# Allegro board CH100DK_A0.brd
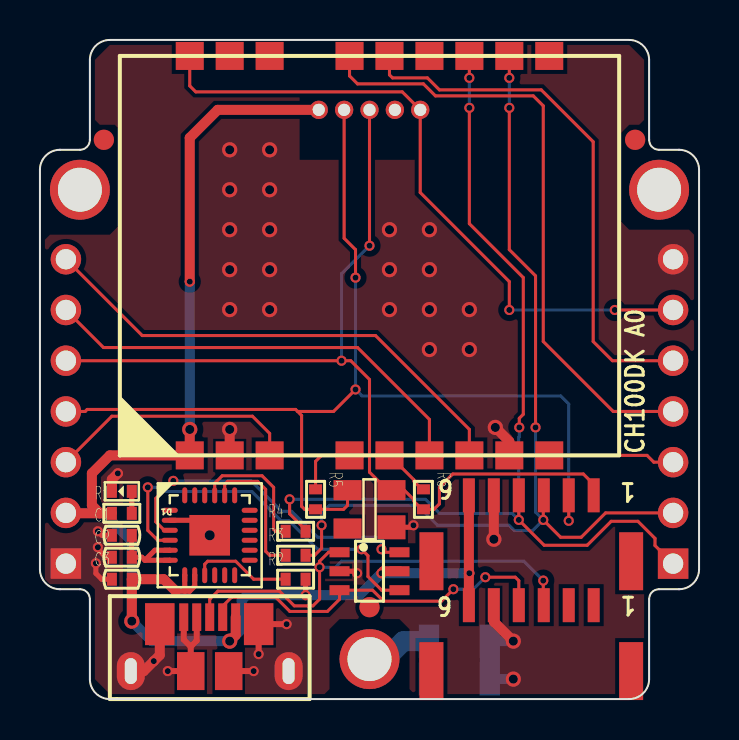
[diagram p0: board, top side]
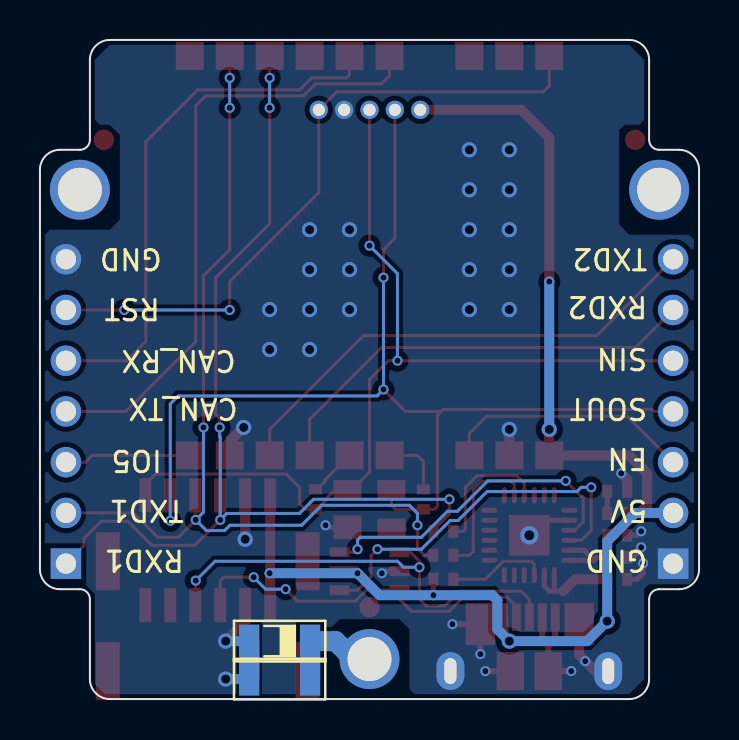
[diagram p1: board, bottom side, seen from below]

Outline 33 x 33 mm; copper layers: TOP, BOTTOM. Coordinates in mm from the lower left corner of the outline.
Outline path: 0,26.5 0,6.5 arc(0.29,5.79) 1,5.5 2,5.5 arc(2.35,5.35) 2.5,5 2.5,1 arc(2.79,0.29) 3.5,0 29.5,0 arc(30.21,0.29) 30.5,1 30.5,5 arc(30.65,5.35) 31,5.5 32,5.5 arc(32.71,5.79) 33,6.5 33,26.5 arc(32.71,27.21) 32,27.5 31,27.5 arc(30.65,27.65) 30.5,28 30.5,32 arc(30.21,32.71) 29.5,33 3.5,33 arc(2.79,32.71) 2.5,32 2.5,28 arc(2.35,27.65) 2,27.5 1,27.5 arc(0.29,27.21) 0,26.5

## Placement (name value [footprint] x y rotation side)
C1  1uF  [C0402]  4.1 8.2 0 top
C2  0.1uF  [C0402]  4.1 7.1 0 top
C3  1uF  [C0402]  4.1 6 0 top
C13  1000pF 1KV  [SC1206]  21 2.9 0 bottom
D1  RED  [LED0402]  4.1 10.4 180 top
D6  SR05  [SOT-143]  16.5 9.5 90 top
H1  HOLE  [HOLE-2-MM]  16.5 2 0 top
H2  HOLE  [HOLE-2-MM]  2 25.5 0 top
H3  HOLE  [HOLE-2-MM]  31 25.5 0 top
J1  MINI-USB  [MICRO-USB-B-1051640001]  8.5 4.1 90 top
J2  HEADER 5  [HEADER1X5-1_27MM]  16.5 29.5 0 bottom
J3  CON6  [A1257WV-S-6P]  24.6 4.7 180 top
J4  CON6  [A1257WV-S-6P]  24.6 10.2 180 top
J5  CON7  [HEADER1X7-2_54MM]  31.7 14.4 90 top
J6  CON7  [HEADER1X7-2_54MM]  1.3 14.4 90 top
NOREF  -  []  2 25.5 0 top
R1  330R  [R0402]  4.1 9.3 0 top
R2  4.7K  [R0402]  12.8 6 0 top
R3  1K  [R0402]  12.8 7.2 0 top
R4  1K  [R0402]  12.8 8.4 0 top
R5  1K  [R0402]  13.8 10 270 top
R6  1K  [R0402]  19.2 10 270 top
R21  1M  [SR1206]  21 1 180 bottom
TP1  TestPoint  [TP-C-40]  3.2 28 0 top
TP2  TestPoint  [TP-C-40]  29.8 28 0 top
TP3  TestPoint  [TP-C-40]  16.5 4.6 0 top
U1  USBLC6-2SC6  [SOT23-6-0_95]  16.5 6.4 270 top
U2  CP2104  [QFN-24_4X4MM_P0_5]  8.5 8.2 0 top
U3  CH100  [CH100_MINI]  16.5 22.2 90 top

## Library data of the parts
C1-C3 C13 = Capacity_Nonpolarity
D1 = LED
D6 = SP0503BAHT
H1-H3 = HOLE
J1 = MICRO-USB_B
J2 = HEADER 5
J3 J4 = CON6
J5 J6 = CON7
R1-R6 R21 = Res
TP1-TP3 = TestPoint
U1 = USBLC6-2SC6
U2 = CP2104
U3 = CH100

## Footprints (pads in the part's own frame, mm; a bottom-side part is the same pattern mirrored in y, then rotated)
A1257WV-S-6P
  rect 1.2x2.9 smd: (-5,3.3) (5,3.3)
  rect 0.6x1.7 smd: 1(-3.125,0) 2(-1.875,0) 3(-0.625,0) 4(0.625,0) 5(1.875,0) 6(3.125,0)
C0402
  rect 0.5x0.65 smd: 1(-0.5,0) 2(0.5,0)
CH100_MINI
  rect 1.4x1.4 smd: 1(-10,9) 2(-10,7) 3(-10,5) 4(-10,1) 5(-10,-1) 6(-10,-3) 7(-10,-5) 8(-10,-7) 9(-10,-9) 10(10,-9) 11(10,-7) 12(10,-5) 13(10,-3) 14(10,-1) 15(10,1) 16(10,5) 17(10,7) 18(10,9)
HEADER1X5-1_27MM
  round 0.914 hole 0.61: 1(-2.54,0) 2(-1.27,0) 3(0,0) 4(1.27,0) 5(2.54,0)
HEADER1X7-2_54MM
  rect 1.524x1.524 hole 1.016: 1(-7.62,0)
  round 1.524 hole 1.016: 2(-5.08,0) 3(-2.54,0) 4(0,0) 5(2.54,0) 6(5.08,0) 7(7.62,0)
HOLE-2-MM
  round 3 hole 2.2: 1(0,0)
LED0402
  rect 0.5x0.65 smd: 1(-0.5,0) 2(0.5,0)
MICRO-USB-B-1051640001
  rect 1.38x0.45 smd: 1(0,-1.3) 2(0,-0.65) 3(0,0) 4(0,0.65) 5(0,1.3)
  rect 2.1x1.475 smd: 6(-0.35,-2.45) 9(-0.35,2.5)
  oval 1.9x1.4 hole 1.3x0.6: 7(-2.7,3.95) 8(-2.7,-3.95)
  rect 1.9x1.375 smd: 10(-2.7,-0.95) 11(-2.7,0.95)
QFN-24_4X4MM_P0_5
  oval 0.8x0.25 smd: 1(-2,1.25) 2(-2,0.75) 3(-2,0.25) 4(-2,-0.25) 5(-2,-0.75) 6(-2,-1.25) 13(2,-1.25) 14(2,-0.75) 15(2,-0.25) 16(2,0.25) 17(2,0.75) 18(2,1.25)
  oval 0.25x0.8 smd: 7(-1.25,-2) 8(-0.75,-2) 9(-0.25,-2) 10(0.25,-2) 11(0.75,-2) 12(1.25,-2) 19(1.25,2) 20(0.75,2) 21(0.25,2) 22(-0.25,2) 23(-0.75,2) 24(-1.25,2)
  rect 2.032x2.032 smd: 25(0,0)
R0402
  rect 0.5x0.65 smd: 1(-0.5,0) 2(0.5,0)
SC1206
  rect 1.016x1.651 smd: 1(-1.524,0) 2(1.524,0)
SOT23-6-0_95
  rect 0.5x1 smd: 1(-0.95,-1.5) 2(0,-1.5) 3(0.95,-1.5) 4(0.95,1.5) 5(0,1.5) 6(-0.95,1.5)
SOT-143
  rect 1.2x1.4 smd: 1(-0.9,-1.1)
  rect 1x1.4 smd: 2(0.96,-1.1) 3(0.96,1.1) 4(-0.96,1.1)
SR1206
  rect 1.016x1.651 smd: 1(-1.524,0) 2(1.524,0)
TP-C-40
  round 1.016 smd: 1(0,0)

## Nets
GND: C1.1 C2.1 C3.1 C13.2 D1.2(-) D6.1 J1.4(ID) J1.5(GND) J1.6 J1.7 J1.8 J1.9 J1.10 J1.11 J2.4 J3.5 J4.5 J5.7 J6.1 R21.1 U1.2(GND) U2.2(GND) U2.25(EPD) U3.2(GND#2) U3.8(GND#8)
CAN_RX: J5.5 U3.14(CAN_RX)
CAN_TX: J5.4 U3.15(CAN_TX)
CP2104_RXD: R3.1 U2.20(RXD)
CP2104_TXD: R4.1 U2.21(TXD)
DN: J1.2(DN) J3.4 U1.3(IO2#3)
DP: J1.3(DP) J3.3 U1.1(IO1#1)
DP5V: C3.2 J1.1(VBUS) J2.1 J3.6 J4.6 J6.2 R1.1 R2.2 U1.5(VBUS) U2.7(REGIN) U2.8(VBUS) U3.1(VCC)
EN: J6.3 U3.3(EN)
IMU_RXD1: J4.4 J5.1 R4.2 U3.12(RXD1)
IMU_TXD1: J4.3 J5.2 R3.2 U3.11(TXD1)
IO5: J5.3 U3.9(IO5)
NRST: J2.5 J5.6 U3.18(NRST)
RXD2: J6.6 U3.6(RXD2)
SYNC_IN: D6.2 J2.3 J4.1 J6.5 R6.2
SYNC_OUT: D6.3 J2.2 J4.2 J6.4 R5.2
TXD2: J6.7 U3.7(TXD2)
USB_DN: U1.4(IO2#4) U2.4(D-)
USB_DP: U1.6(IO1#6) U2.3(D+)
N02222: C1.2 C2.2 U2.5(VIO) U2.6(VDD)
N03180: R2.1 U2.9(R\S\T\)
N94151: D1.1(+) R1.2
N722959: R5.1 U3.4(SYNC_OUT)
N722963: R6.1 U3.5(SYNC_IN)
N726760: C13.1 H1.1 R21.2

Pads without a net: D6 4; H2 1; H3 1; J3 1 2; TP1 1; TP2 1; TP3 1; U2 1 10 11 12 13 14 15 16 17 18 19 22 23 24; U3 10 13 16 17

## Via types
v1: diameter 0.508, hole 0.305, TOP to BOTTOM, 40 vias
v2: diameter 0.762, hole 0.457, TOP to BOTTOM, 27 vias
v3: diameter 0.914, hole 0.508, TOP to BOTTOM, 1 via

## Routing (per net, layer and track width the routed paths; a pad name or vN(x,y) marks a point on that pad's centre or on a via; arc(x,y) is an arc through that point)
GND: length 33.6
  TOP w0.254: C1.1 3.1,8.2 v1(2.9,8.4) ; C3.1 3.09,6 2.8,6.29 v1(2.8,6.8) ; D6.1 18.6,8.6 v1(18.7,8.7) ; v1(15.88,6.3) 15.8,6.3 15.7,6.4 U1.2 ; v1(2.9,7.6) 2.9,7.5 3.3,7.1 C2.1 ; U2.2 7.75,8.95 v3(8.5,8.2)
  TOP w0.3: J1.4 7.85,2.93 7.55,2.63 ; v1(10.95,2.25) J1.6 v1(12.35,3.75) ; 7.55,2.63 7.2,2.98 J1.5 ; 7.55,2.63 J1.11 v1(6.4,1.4) ; J1.10 v1(10.7,1.4)
  TOP w0.4: 1.62,6.78 J6.1
  TOP w0.5: v1(3.9,11.3) 3.6,11 D1.2 ; U3.2 v2(9.5,13.5) ; J4.5 v2(22.72,8) ; v2(22.8,13.6) 23.5,12.9 U3.8 ; J1.9 6,2.2 v1(5.7,1.9) 5.2,1.4 J1.7 ; v2(23.7,2.9) 22.72,3.87 J3.5
  BOTTOM w0.5: R21.1 v2(23.7,1) ; C13.2 v2(23.7,2.9)
  BOTTOM w1: R21.1 C13.2
  vias: v2(9.5,27.5) v2(9.5,25.5) v2(9.5,23.5) v2(9.5,21.5) v2(9.5,19.5) v2(11.5,27.5) v2(11.5,25.5) v2(11.5,23.5) v2(11.5,21.5) v2(11.5,19.5) v2(17.5,23.5) v2(17.5,21.5) v2(17.5,19.5) v2(19.5,23.5) v2(19.5,21.5) v2(19.5,19.5) v2(19.5,17.5) v2(21.5,19.5) v2(21.5,17.5)
CAN_RX: length 26.9
  TOP w0.152: U3.14 17.5,31.25 17.65,31.1 19.4,31.1 20,30.5 25.1,30.5 27.7,27.9 27.7,17.9 28.66,16.94 J5.5
CAN_TX: length 31.1
  TOP w0.152: U3.15 15.5,31.2 15.9,30.8 19.2,30.8 19.8,30.2 24.7,30.2 25.2,29.7 25.2,17.9 28.7,14.4 J5.4
CP2104_RXD: length 7
  TOP w0.152: R3.1 11.5,7.2 11.3,7.4 11.3,10.5 10.9,10.9 9.4,10.9 9.25,10.75 U2.20
CP2104_TXD: length 6.7
  TOP w0.152: U2.21 8.75,10.8 9.13,11.18 11.12,11.18 11.7,10.6 11.7,8.5 11.8,8.4 R4.1
DN: length 18.6
  TOP w0.152: J3.4 23.97,4.7 23.97,5.92 23.8,6.1 v1(22.3,6.1) ; J1.2 9.15,4.65 9.6,5.1 11.8,5.1 12.51,4.39 14.39,4.39 15,5 U1.3 16.66,5.45 17.21,4.9 20.1,4.9 v1(20.7,5.5)
  BOTTOM w0.152: v1(20.7,5.5) 21.7,5.5 v1(22.3,6.1)
DP: length 23.1
  TOP w0.152: J1.3 8.5,4.99 8.91,5.4 12,5.4 12.73,4.67 13.67,4.67 14,5 v1(14,6.6) 14,6.9 14.45,7.35 U1.1 ; v1(25.2,5.93) 25.2,4.72 J3.3
  BOTTOM w0.152: v1(14,6.6) 14.8,6.6 15.1,6.9 24.23,6.9 v1(25.2,5.93)
DP5V: length 75.7
  TOP w0.254: 7.26,5.4 6.8,5.4 ; 7.26,5.4 7.5,5.4 7.75,5.65 U2.8 ; 7.26,5.4 7.25,5.41 U2.7 ; R2.2 v1(13.3,5.2)
  TOP w0.5: U1.5 17.2,6.4 v1(17.1,6.3) ; 21.47,6.27 21.47,10.2 J4.6 ; 21.47,6.27 21.47,4.7 J3.6 ; 21.47,6.27 v1(21.5,6.3) ; J2.1 8.9,29.5 7.5,28.1 v1(7.5,20.9) ; 6.8,5.4 6.2,6 C3.2 v2(4.6,3.9) ; J6.2 1.32,9.3 3,9.3 ; v2(7.5,13.5) U3.1 3.5,12.2 2.6,11.3 2.6,9.7 3,9.3 ; 3,9.3 R1.1 ; J1.1 9.8,3.2 v2(9.5,2.9)
  BOTTOM w0.5: v1(21.5,6.3) v1(17.1,6.3) 16,5.2 v1(13.3,5.2) 10.35,5.2 10.1,4.95 10.1,3.5 v2(9.5,2.9) 5.6,2.9 v2(4.6,3.9) 4.6,7.9 3.18,9.32 J6.2 ; v2(7.5,13.5) v1(7.5,20.9)
EN: length 12.6
  TOP w0.152: J6.3 3.6,14.16 10.64,14.16 11.5,13.3 U3.3
IMU_RXD1: length 49.3
  TOP w0.152: J4.4 23.97,10.2 v1(23.97,8.97) 25.24,7.7 27.4,7.7 28.6,8.9 29.94,8.9 30.79,8.04 30.79,7.69 J5.1 ; R4.2 13.3,8.47 12.5,9.27 v1(12.5,10) ; v1(24,13.6) 24,14.06 24.2,14.26 24.2,21.1 21.5,23.8 v1(21.5,29.6) ; U3.12 v1(21.5,31.1)
  BOTTOM w0.152: v1(21.5,31.1) v1(21.5,29.6) ; v1(12.5,10) 19.3,10 20.01,9.29 23.65,9.29 v1(23.97,8.97) 23.97,13.12 24,13.14 v1(24,13.6)
IMU_TXD1: length 47.2
  TOP w0.152: J5.2 28.32,9.32 27.1,8.1 26.07,8.1 v1(25.2,8.97) 25.2,10.17 J4.3 ; R3.2 13.75,7.2 14.1,7.55 v1(14.1,8.7) ; U3.11 v1(23.5,31.1) ; v1(23.5,29.6) 23.5,22.5 24.81,21.19 v1(24.81,13.6)
  BOTTOM w0.152: v1(23.5,31.1) v1(23.5,29.6) ; v1(14.1,8.7) 14.1,9.3 14.5,9.7 18.9,9.7 19.9,8.7 23.49,8.7 23.75,8.44 24.67,8.44 v1(25.2,8.97) 24.81,9.36 v1(24.81,13.6)
IO5: length 6.3
  TOP w0.152: J5.3 30.73,11.86 30.39,12.2 U3.9
NRST: length 33.6
  TOP w0.152: v1(23.5,19.48) 23.5,20.9 19.04,25.36 J2.5 18.14,30.4 7.8,30.4 7.5,30.7 U3.18 ; J5.6 v1(28.78,19.48)
  BOTTOM w0.152: v1(28.78,19.48) v1(23.5,19.48)
RXD2: length 22.3
  TOP w0.152: J6.6 3.18,17.6 15.9,17.6 19.5,14 U3.6
SYNC_IN: length 47.4
  TOP w0.152: J6.5 v1(15.1,16.94) 15.56,16.94 16.5,16 16.5,11.36 17.4,10.46 D6.2 18.24,10.46 18.73,9.97 18.73,9.89 19.13,9.5 R6.2 19.73,9.5 20,9.77 20,10.6 20.67,11.27 27.21,11.27 27.72,10.75 J4.1 ; J2.3 v1(16.5,22.7)
  BOTTOM w0.152: v1(15.1,16.94) 15.1,21.3 v1(16.5,22.7)
SYNC_OUT: length 55.4
  TOP w0.152: 12.9,14.4 13.1,14.2 13.1,9.65 13.25,9.5 R5.2 15.2,9.5 15.4,9.7 D6.3 ; 12.9,14.4 12.8,14.5 2.37,14.5 2.27,14.4 J6.4 ; 12.9,14.4 14.7,14.4 v1(15.8,15.5) ; v1(15.8,21.1) 15.8,22.5 15.23,23.07 J2.2 ; J4.2 v1(26.48,8.93)
  BOTTOM w0.152: v1(26.48,8.93) 26.48,14.78 26.07,15.18 16.12,15.18 v1(15.8,15.5) v1(15.8,21.1)
TXD2: length 25
  TOP w0.152: U3.7 21.5,13.5 16.8,18.2 5.12,18.2 J6.7
USB_DN: length 18.8
  TOP w0.152: U1.4 17.11,5.45 16.42,6.13 16.42,7.18 v1(16.1,7.5) ; U2.4 5.9,7.95 5.4,8.45 v1(5.4,10.6)
  BOTTOM w0.152: v1(5.4,10.6) 5.9,10.6 6.11,10.39 10.61,10.39 12.06,8.94 12.46,8.94 13.9,7.5 v1(16.1,7.5)
USB_DP: length 16.4
  TOP w0.152: v1(6.68,10.92) 5.8,10.05 5.8,8.87 6.22,8.45 U2.3 ; v1(17.1,7.5) 17.25,7.35 U1.6
  BOTTOM w0.152: v1(6.68,10.92) 10.58,10.92 12.1,9.4 12.6,9.4 13.9,8.1 16.96,8.1 17.1,7.96 v1(17.1,7.5)
N02222: length 4.5
  TOP w0.254: C1.2 C2.2 5.1,7.1 5.25,6.95 ; 5.25,6.95 U2.6 ; 5.25,6.95 5.75,7.45 U2.5
N03180: length 5
  TOP w0.152: R2.1 10.7,6 9.8,6.9 8.4,6.9 8.25,6.75 U2.9
N94151: length 1.1
  TOP w0.254: R1.2 D1.1
N722959: length 3.2
  TOP w0.152: R5.1 13.8,11.9 14.1,12.2 U3.4
N722963: length 2.4
  TOP w0.152: R6.1 19.13,10.5 18.73,10.89 18.73,10.97 U3.5
N726760: length 5.2
  BOTTOM w1: R21.2 C13.1 18.2,2.9 17.3,2 H1.1

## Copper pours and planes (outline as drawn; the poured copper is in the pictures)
GND on TOP: 14.5,0.5 14.25,0.25 3.5,0.25 2.75,1 2.75,5.5 2.5,5.75 0.5,5.75 0.25,6 0.25,23 0.5,23.25 3.5,23.25 4,23.75 4,28.5 3.75,28.75 3,28.75 2.75,29 2.75,32 3.5,32.75 29.5,32.75 30.25,32 30.25,29 30,28.75 29.5,28.75 29,28.25 29,24 29.5,23.5 32.5,23.5 32.75,23.25 32.75,6.25 32.25,5.75 30.75,5.75 30.25,5.25 30.25,0.75 29.75,0.25 18.75,0.25 18.5,0.5 18.5,3.5 18,4 15,4 14.5,3.5 ; 36 cut-outs
GND on BOTTOM: 14.25,0.25 3.5,0.25 2.75,1 2.75,5.5 2.5,5.75 0.5,5.75 0.25,6 0.25,23 0.5,23.25 3.5,23.25 4,23.75 4,28.5 3.75,28.75 3,28.75 2.75,29 2.75,32 3.5,32.75 29.5,32.75 30.25,32 30.25,29 30,28.75 29.5,28.75 29,28.25 29,24 29.5,23.5 32.5,23.5 32.75,23.25 32.75,6.25 32.25,5.75 30.75,5.75 30.25,5.25 30.25,0.75 29.75,0.25 18.75,0.25 18.5,0.5 18.5,3.5 18,4 15,4 14.5,3.5 14.5,0.5 ; 4 cut-outs

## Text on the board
Ref Des/Silkscreen Bottom: TXD2 | RXD2 | SIN | SOUT | EN | 5V | GND | CAN_TX | CAN_RX | TXD1 | RXD1 | IO5 | RST
Ref Des/Silkscreen Top: CH100DK A0 | 6 | 1
